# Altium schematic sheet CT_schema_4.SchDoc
size 221 x 258 mm
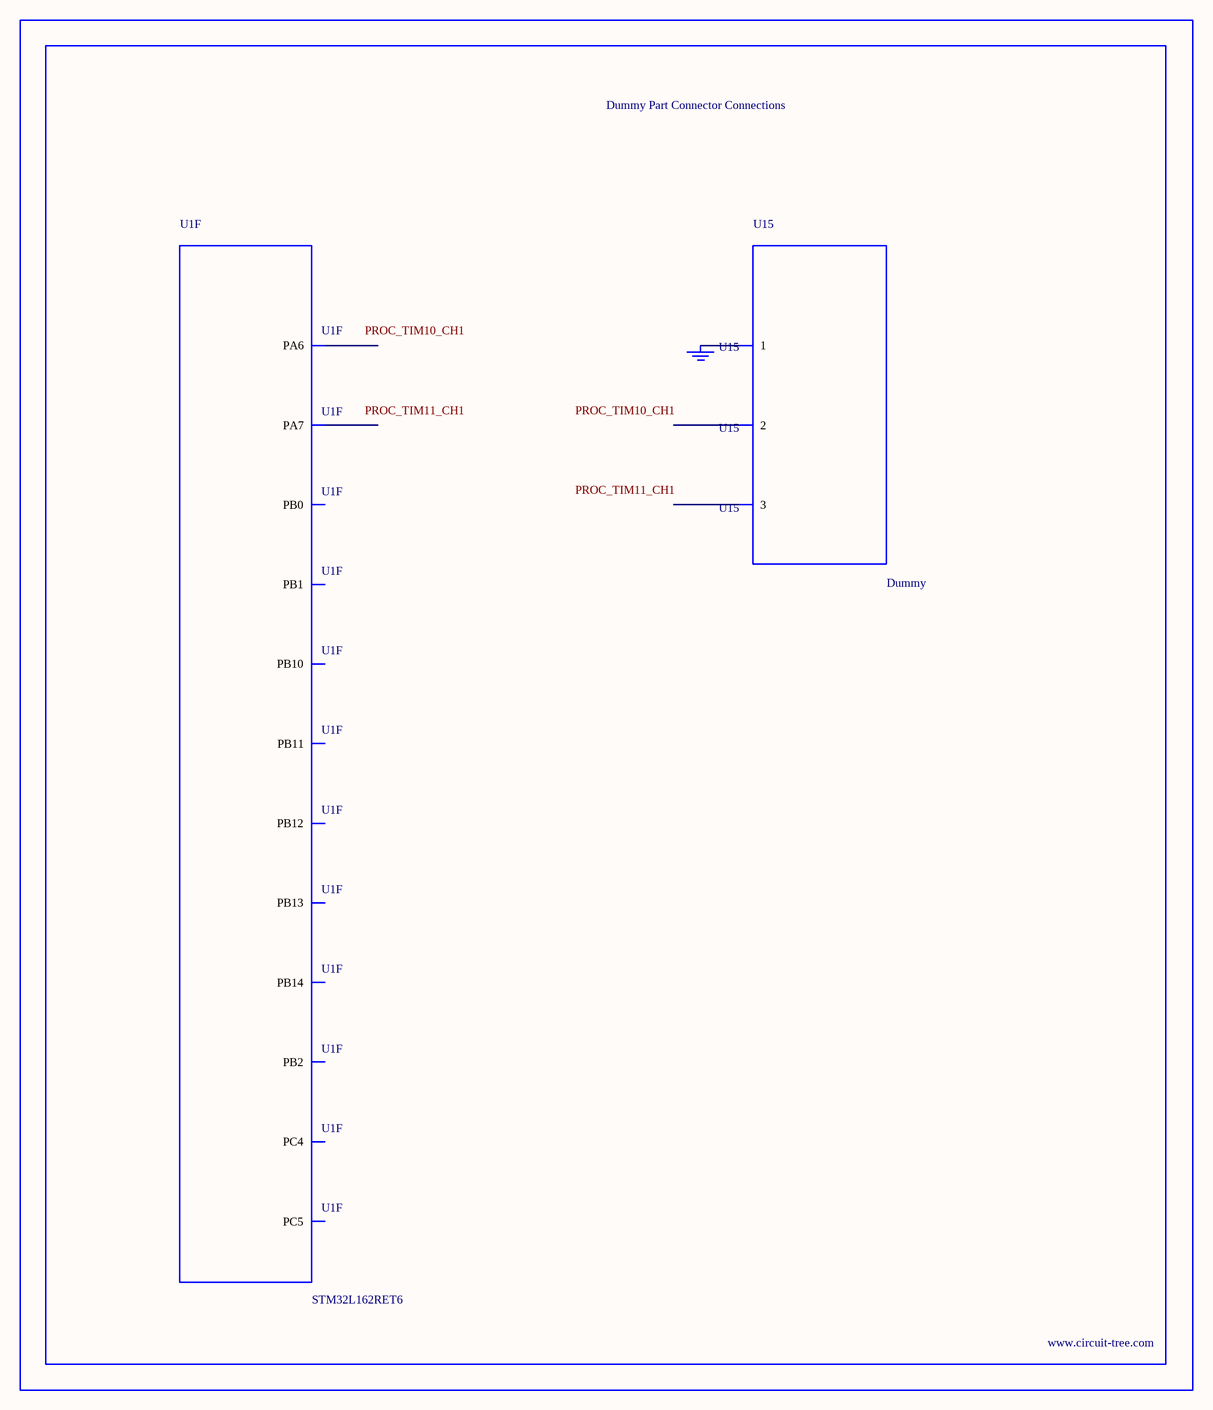
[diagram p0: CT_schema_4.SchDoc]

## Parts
BORDER3  (no value)
GND_INSTANCE_3_0  (no value)
U1  STM32L162RET6  [LQFP64]  (part F of 6)
U15  Dummy  [DUMMY_PACKAGE_113]

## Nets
NetGND_INSTANCE_3_0_0: GND_INSTANCE_3_0.0(GND) U15.1

Not connected (* = marked no-connect by the designer): U1 22(PA6) 23(PA7) 24(PC4) 25(PC5) 26(PB0) 27(PB1) 28(PB2) 29(PB10) 30(PB11) 33(PB12) 34(PB13) 35(PB14); U15 2 3

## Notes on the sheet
- Labels drawn without touching a wire or pin: PROC_TIM10_CH1, PROC_TIM11_CH1

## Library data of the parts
BORDER3 = BORDER_PAGE3
GND_INSTANCE_3_0 = GND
